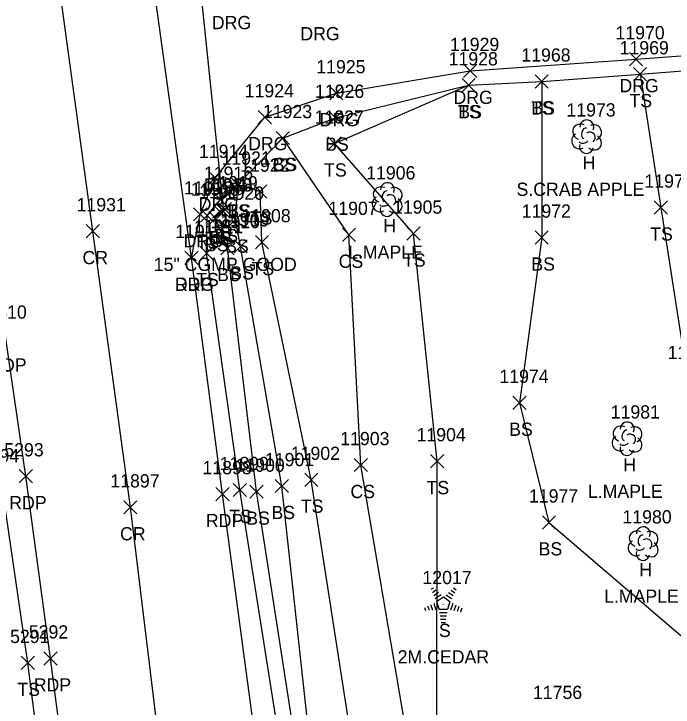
# Model space of a CAD drawing. Extents: x 1439173 to 1457902, y 641926 to 659889.
# Drawn here: x 1447875.7 to 1447975.3, y 648924.6 to 649029.4 of the extents above; entities that cross this region are included whole.
import ezdxf

# ---------------------------------------------------------------- set-up
doc = ezdxf.new("R2010")
doc.units = 0
for name, color, linetype in [('D_A', 7, 'Continuous'), ('D_C', 7, 'Continuous'), ('D_I', 7, 'Continuous'), ('D_TIC', 7, 'Continuous'), ('DCP', 7, 'Continuous'), ('L_A', 7, 'Continuous'), ('L_C', 7, 'Continuous'), ('L_I', 7, 'Continuous'), ('L_TIC', 7, 'Continuous'), ('LELB', 7, 'Continuous'), ('LTC', 7, 'Continuous'), ('LTD', 7, 'Continuous'), ('P_A', 7, 'Continuous'), ('P_I', 7, 'Continuous'), ('P_TIC', 7, 'Continuous'), ('PET', 7, 'Continuous'), ('PRC', 7, 'Continuous'), ('R_A', 7, 'Continuous'), ('R_I', 7, 'Continuous'), ('R_TIC', 7, 'Continuous'), ('RDG', 7, 'Continuous')]:
    doc.layers.add(name, color=color, linetype=linetype)

msp = doc.modelspace()

# ---------------------------------------------------------------- linework, layer by layer
at = {"layer": 'D_TIC'}
for points in [[(1447906.42, 648998.53), (1447908.42, 649000.53)], [(1447908.42, 648998.53), (1447906.42, 649000.53)]]:
    msp.add_lwpolyline(points, dxfattribs=at)
at = {"layer": 'DCP'}
msp.add_lwpolyline([(1447907.42, 648999.53), (1447903.2, 649040.33)], dxfattribs=at)
at = {"layer": 'L_TIC'}
for points in [[(1447969.33, 649019.28), (1447971.33, 649021.28)], [(1447971.33, 649019.28), (1447969.33, 649021.28)], [(1447969.33, 649019.28), (1447971.33, 649021.28)], [(1447971.33, 649019.28), (1447969.33, 649021.28)], [(1447954.47, 649018.18), (1447956.47, 649020.18)], [(1447956.47, 649018.18), (1447954.47, 649020.18)], [(1447954.47, 649018.18), (1447956.47, 649020.18)], [(1447956.47, 649018.18), (1447954.47, 649020.18)], [(1447943.43, 649017.61), (1447945.43, 649019.61)], [(1447945.43, 649017.61), (1447943.43, 649019.61)], [(1447943.43, 649017.61), (1447945.43, 649019.61)], [(1447945.43, 649017.61), (1447943.43, 649019.61)], [(1447923.3, 649012.7), (1447925.3, 649014.7)], [(1447925.3, 649012.7), (1447923.3, 649014.7)], [(1447915.36, 649009.63), (1447917.36, 649011.63)], [(1447917.36, 649009.63), (1447915.36, 649011.63)], [(1447915.36, 649009.63), (1447917.36, 649011.63)], [(1447917.36, 649009.63), (1447915.36, 649011.63)], [(1447923.18, 649008.8), (1447925.18, 649010.8)], [(1447925.18, 649008.8), (1447923.18, 649010.8)], [(1447908.54, 649002.59), (1447910.54, 649004.59)], [(1447910.54, 649002.59), (1447908.54, 649004.59)], [(1447908.54, 649002.59), (1447910.54, 649004.59)], [(1447910.54, 649002.59), (1447908.54, 649004.59)], [(1447911.95, 649001.53), (1447913.95, 649003.53)], [(1447913.95, 649001.53), (1447911.95, 649003.53)], [(1447911.95, 649001.53), (1447913.95, 649003.53)], [(1447913.95, 649001.53), (1447911.95, 649003.53)], [(1447905.94, 649000.32), (1447907.94, 649002.32)], [(1447907.94, 649000.32), (1447905.94, 649002.32)], [(1447905.81, 648998.55), (1447907.81, 649000.55)], [(1447907.81, 648998.55), (1447905.81, 649000.55)], [(1447906.58, 648998.87), (1447908.58, 649000.87)], [(1447908.58, 648998.87), (1447906.58, 649000.87)], [(1447972.46, 648999.12), (1447974.46, 649001.12)], [(1447974.46, 648999.12), (1447972.46, 649001.12)], [(1447903.91, 648997.9), (1447905.91, 648999.9)], [(1447905.91, 648997.9), (1447903.91, 648999.9)], [(1447905.16, 648997.51), (1447907.16, 648999.51)], [(1447907.16, 648997.51), (1447905.16, 648999.51)], [(1447908.19, 648997.29), (1447910.19, 648999.29)], [(1447910.19, 648997.29), (1447908.19, 648999.29)], [(1447908.19, 648997.29), (1447910.19, 648999.29)], [(1447910.19, 648997.29), (1447908.19, 648999.29)], [(1447925.35, 648995), (1447927.35, 648997)], [(1447927.35, 648995), (1447925.35, 648997)], [(1447935.11, 648995.19), (1447937.11, 648997.19)], [(1447937.11, 648995.19), (1447935.11, 648997.19)], [(1447954.47, 648994.58), (1447956.47, 648996.58)], [(1447956.47, 648994.58), (1447954.47, 648996.58)], [(1447906.99, 648992.99), (1447908.99, 648994.99)], [(1447908.99, 648992.99), (1447906.99, 648994.99)], [(1447908.98, 648993.25), (1447910.98, 648995.25)], [(1447910.98, 648993.25), (1447908.98, 648995.25)], [(1447912.2, 648993.89), (1447914.2, 648995.89)], [(1447914.2, 648993.89), (1447912.2, 648995.89)], [(1447903.84, 648992.23), (1447905.84, 648994.23)], [(1447905.84, 648992.23), (1447903.84, 648994.23)], [(1447951.11, 648969.6), (1447953.11, 648971.6)], [(1447953.11, 648969.6), (1447951.11, 648971.6)], [(1447938.66, 648960.78), (1447940.66, 648962.78)], [(1447940.66, 648960.78), (1447938.66, 648962.78)], [(1447927.13, 648960.19), (1447929.13, 648962.19)], [(1447929.13, 648960.19), (1447927.13, 648962.19)], [(1447919.66, 648957.97), (1447921.66, 648959.97)], [(1447921.66, 648957.97), (1447919.66, 648959.97)], [(1447908.85, 648956.42), (1447910.85, 648958.42)], [(1447910.85, 648956.42), (1447908.85, 648958.42)], [(1447915.19, 648957.02), (1447917.19, 648959.02)], [(1447917.19, 648957.02), (1447915.19, 648959.02)], [(1447911.39, 648956.17), (1447913.39, 648958.17)], [(1447913.39, 648956.17), (1447911.39, 648958.17)], [(1447955.57, 648951.52), (1447957.57, 648953.52)], [(1447957.57, 648951.52), (1447955.57, 648953.52)], [(1447876.83, 648930.28), (1447878.83, 648932.28)], [(1447878.83, 648930.28), (1447876.83, 648932.28)]]:
    msp.add_lwpolyline(points, dxfattribs=at)
at = {"layer": 'LELB'}
for points in [[(1447887.67, 648779.22), (1447894.83, 648793.53), (1447889.54, 648830.77), (1447886.45, 648861.56), (1447882.46, 648894.79), (1447877.83, 648931.28), (1447873.82, 648958.59), (1447871.58, 648979.94), (1447867.78, 649009.27), (1447863.09, 649046), (1447856.74, 649083.7)], [(1447970.33, 649020.28), (1448000.68, 649022.67), (1448022.54, 649027.2)], [(1447939.65, 648917.11), (1447939.66, 648961.78), (1447936.11, 648996.19), (1447924.18, 649009.8), (1447944.43, 649018.61), (1447955.47, 649019.18), (1447970.33, 649020.28), (1447973.46, 649000.12), (1447977.53, 648974.21), (1447988.81, 648949.77)], [(1447955.47, 649019.18), (1447955.47, 648995.58), (1447952.11, 648970.6), (1447956.57, 648952.52), (1447981.81, 648930.91)], [(1447974.79, 648514.27), (1447972.12, 648545.7), (1447967.29, 648596.82), (1447958.07, 648647.1), (1447953.07, 648690.28), (1447946.6, 648739.03), (1447940.66, 648780.96), (1447936.37, 648827.1), (1447928.59, 648872.23), (1447920.72, 648916.47), (1447916.19, 648958.02), (1447909.98, 648994.25), (1447909.19, 648998.29), (1447909.54, 649003.59), (1447916.36, 649010.63), (1447924.3, 649013.7), (1447944.43, 649018.61)], [(1447949.69, 648749.17), (1447957, 648759.34), (1447950.28, 648781.04), (1447942.95, 648828.32), (1447936.39, 648874.41), (1447936.04, 648914.65), (1447928.13, 648961.19), (1447926.35, 648996), (1447916.36, 649010.63)], [(1447969.85, 648514.47), (1447964.49, 648544.65), (1447957.95, 648597.38), (1447952.29, 648645.71), (1447946.98, 648689.75), (1447940.5, 648738.3), (1447934.59, 648780.28), (1447929.04, 648824.88), (1447922.4, 648871.3), (1447916.32, 648916.62), (1447909.85, 648957.42), (1447904.84, 648993.23), (1447904.91, 648998.9), (1447906.94, 649001.32), (1447909.54, 649003.59), (1447912.95, 649002.53)], [(1447957.48, 648693.42), (1447950, 648739.49), (1447949.69, 648749.17), (1447943.12, 648781.41), (1447938.92, 648828.83), (1447932.09, 648872.31), (1447927.36, 648915.79), (1447920.66, 648958.97), (1447913.2, 648994.89), (1447912.95, 649002.53)], [(1447971.97, 648514.34), (1447968.59, 648545.51), (1447962.76, 648598.05), (1447955.08, 648646.1), (1447949.31, 648689.51), (1447943.88, 648738.57), (1447940.65, 648781.02), (1447931.82, 648826.68), (1447925.82, 648871.76), (1447918.72, 648916.18), (1447912.39, 648957.17), (1447907.99, 648993.99), (1447906.16, 648998.51), (1447906.81, 648999.55), (1447907.58, 648999.87), (1447909.19, 648998.29)]]:
    msp.add_lwpolyline(points, dxfattribs=at)
at = {"layer": 'LTC'}
for p, q in [((1447938.75, 648942.4), (1447939.1, 648942.65)), ((1447942.15, 648942.64), (1447942.57, 648942.33)), ((1447938.96, 648941.93), (1447939.49, 648942.31)), ((1447939.17, 648941.46), (1447939.87, 648941.98)), ((1447939.38, 648941), (1447940.26, 648941.64)), ((1447941.03, 648941.59), (1447941.84, 648941)), ((1447941.41, 648941.94), (1447942.08, 648941.45)), ((1447941.78, 648942.29), (1447942.33, 648941.89)), ((1447939.6, 648940.54), (1447940.61, 648941.28)), ((1447939.6, 648940.54), (1447939.99, 648939.35)), ((1447940.61, 648941.28), (1447941.61, 648940.55)), ((1447941.61, 648940.55), (1447941.22, 648939.35)), ((1447937.78, 648939.67), (1447937.93, 648939.21)), ((1447938.24, 648939.89), (1447938.45, 648939.24)), ((1447938.69, 648940.11), (1447938.96, 648939.27)), ((1447939.15, 648940.32), (1447939.48, 648939.3)), ((1447941.22, 648939.35), (1447939.99, 648939.35)), ((1447942.05, 648940.28), (1447941.71, 648939.24)), ((1447942.49, 648940.03), (1447942.21, 648939.15)), ((1447942.94, 648939.78), (1447942.7, 648939.05)), ((1447943.38, 648939.53), (1447943.2, 648938.96)), ((1447941.18, 648938.85), (1447940.04, 648938.85)), ((1447941.1, 648938.35), (1447940.11, 648938.35)), ((1447941.01, 648937.85), (1447940.18, 648937.85)), ((1447940.93, 648937.35), (1447940.26, 648937.35))]:
    msp.add_line(p, q, dxfattribs=at)
at = {"layer": 'LTD'}
for p, q in [((1447962.24, 649010.88), (1447962.24, 649010.88)), ((1447962.24, 649010.88), (1447962.24, 649010.88)), ((1447932.1, 649001.37), (1447932.1, 649001.37)), ((1447932.1, 649001.37), (1447932.1, 649001.37)), ((1447968.35, 648965.22), (1447968.35, 648965.22)), ((1447968.35, 648965.22), (1447968.35, 648965.22)), ((1447970.79, 648949.36), (1447970.79, 648949.36)), ((1447970.79, 648949.36), (1447970.79, 648949.36))]:
    msp.add_line(p, q, dxfattribs=at)
for centre in [(1447962.29, 649012.31), (1447932.15, 649002.81), (1447968.4, 648966.65), (1447970.83, 648950.8)]:
    msp.add_arc(centre, 1.05, 335.5272, 180.9563, dxfattribs=at)
for centre, major_axis, ratio, start_param, end_param in [((1447961.45, 649011.54), (1.21, -0.51), 0.895232, 1.570796, 4.712389), ((1447963.28, 649011.46), (-1.14, -0.48), 0.949671, 1.570796, 4.712389), ((1447962.03, 649011.34), (-0.208, -0.792), 0.645439, 3.141593, 6.283185), ((1447962.74, 649010.71), (-0.5, 0.667), 0.989748, 3.141593, 6.283185), ((1447961.16, 649010.17), (0.58, -1.04), 0.959034, 3.141593, 6.283185), ((1447963.24, 649010.04), (-1.09, 0.79), 0.841452, 1.570796, 4.712389), ((1447962.24, 649009.38), (0.26, 1.06), 0.942809, 1.570796, 4.712389), ((1447961.78, 649010.13), (-0.625, -0.083), 0.423636, 0, 3.141593), ((1447931.31, 649002.04), (1.21, -0.51), 0.895232, 1.570796, 4.712389), ((1447933.15, 649001.96), (-1.14, -0.48), 0.949671, 1.570796, 4.712389), ((1447931.9, 649001.83), (-0.208, -0.792), 0.645439, 3.141593, 6.283185), ((1447931.02, 649000.66), (0.58, -1.04), 0.959034, 3.141593, 6.283185), ((1447932.6, 649001.21), (-0.5, 0.667), 0.989748, 3.141593, 6.283185), ((1447933.1, 649000.54), (-1.09, 0.79), 0.841452, 1.570796, 4.712389), ((1447932.11, 648999.87), (0.26, 1.06), 0.942809, 1.570796, 4.712389), ((1447931.65, 649000.62), (-0.625, -0.083), 0.423636, 0, 3.141593), ((1447967.56, 648965.89), (1.21, -0.51), 0.895232, 1.570796, 4.712389), ((1447969.4, 648965.8), (-1.14, -0.48), 0.949671, 1.570796, 4.712389), ((1447967.27, 648964.51), (0.58, -1.04), 0.959034, 3.141593, 6.283185), ((1447968.15, 648965.68), (-0.208, -0.792), 0.645439, 3.141593, 6.283185), ((1447968.85, 648965.05), (-0.5, 0.667), 0.989748, 3.141593, 6.283185), ((1447967.9, 648964.47), (-0.625, -0.083), 0.423636, 0, 3.141593), ((1447969.35, 648964.39), (-1.09, 0.79), 0.841452, 1.570796, 4.712389), ((1447968.35, 648963.72), (0.26, 1.06), 0.942809, 1.570796, 4.712389), ((1447970, 648950.03), (1.21, -0.51), 0.895232, 1.570796, 4.712389), ((1447971.83, 648949.95), (-1.14, -0.48), 0.949671, 1.570796, 4.712389), ((1447970.58, 648949.82), (-0.208, -0.792), 0.645439, 3.141593, 6.283185), ((1447971.29, 648949.2), (-0.5, 0.667), 0.989748, 3.141593, 6.283185), ((1447969.7, 648948.65), (0.58, -1.04), 0.959034, 3.141593, 6.283185), ((1447971.79, 648948.53), (-1.09, 0.79), 0.841452, 1.570796, 4.712389), ((1447970.79, 648947.86), (0.26, 1.06), 0.942809, 1.570796, 4.712389), ((1447970.33, 648948.61), (-0.625, -0.083), 0.423636, 0, 3.141593)]:
    msp.add_ellipse(centre, major_axis=major_axis, ratio=ratio, start_param=start_param, end_param=end_param, dxfattribs=at)
at = {"layer": 'P_TIC'}
for points in [[(1447886.64, 648995.55), (1447888.64, 648997.55)], [(1447888.64, 648995.55), (1447886.64, 648997.55)], [(1447901.54, 648991.52), (1447903.54, 648993.52)], [(1447903.54, 648991.52), (1447901.54, 648993.52)], [(1447876.52, 648958.5), (1447878.52, 648960.5)], [(1447878.52, 648958.5), (1447876.52, 648960.5)], [(1447906.24, 648955.8), (1447908.24, 648957.8)], [(1447908.24, 648955.8), (1447906.24, 648957.8)], [(1447892.31, 648953.8), (1447894.31, 648955.8)], [(1447894.31, 648953.8), (1447892.31, 648955.8)], [(1447880.23, 648930.96), (1447882.23, 648932.96)], [(1447882.23, 648930.96), (1447880.23, 648932.96)]]:
    msp.add_lwpolyline(points, dxfattribs=at)
at = {"layer": 'PET'}
for points in [[(1447899.12, 648797.86), (1447894.84, 648829.94), (1447890.35, 648861.78), (1447886.08, 648894.83), (1447881.23, 648931.96), (1447877.52, 648959.5), (1447874.49, 648980.32), (1447870.94, 649009.61), (1447865.79, 649048.58), (1447861.1, 649084.28)], [(1447985.99, 648352.77), (1447984.12, 648388.61), (1447978.58, 648406.37), (1447976.75, 648417.49), (1447970.56, 648463.48), (1447964.44, 648514.86), (1447960.48, 648544.49), (1447954.4, 648596.97), (1447948.04, 648645.35), (1447942.48, 648689.3), (1447936.15, 648737.63), (1447930.52, 648780.21), (1447924.61, 648825.68), (1447919.43, 648871), (1447912.62, 648916.56), (1447907.24, 648956.8), (1447902.54, 648992.52), (1447895.42, 649044.11)]]:
    msp.add_lwpolyline(points, dxfattribs=at)
at = {"layer": 'PRC'}
msp.add_lwpolyline([(1447922.05, 648736.93), (1447916.64, 648778.15), (1447910.27, 648824.18), (1447904.7, 648868.93), (1447898.12, 648915.43), (1447893.31, 648954.8), (1447887.64, 648996.55), (1447880.91, 649046.05), (1447877.83, 649074.56), (1447871.42, 649121.75), (1447866.3, 649164.93), (1447861.97, 649198.82), (1447856.91, 649237.59), (1447851.83, 649275.88), (1447846.3, 649313.42), (1447840.87, 649352.48), (1447833.11, 649400.15), (1447825.79, 649441.89), (1447815.69, 649490.23), (1447802.04, 649547.27), (1447789.05, 649591.57), (1447772.48, 649642.76), (1447756.88, 649685.17), (1447724.87, 649768.37)], dxfattribs=at)
at = {"layer": 'R_TIC'}
for points in [[(1447968.73, 649021.55), (1447970.73, 649023.55)], [(1447970.73, 649021.55), (1447968.73, 649023.55)], [(1447943.65, 649019.78), (1447945.65, 649021.78)], [(1447945.65, 649019.78), (1447943.65, 649021.78)], [(1447923.44, 649016.41), (1447925.44, 649018.41)], [(1447925.44, 649016.41), (1447923.44, 649018.41)], [(1447912.62, 649012.78), (1447914.62, 649014.78)], [(1447914.62, 649012.78), (1447912.62, 649014.78)], [(1447905.14, 649003.61), (1447907.14, 649005.61)], [(1447907.14, 649003.61), (1447905.14, 649005.61)], [(1447902.86, 648998.09), (1447904.86, 649000.09)], [(1447904.86, 648998.09), (1447902.86, 649000.09)], [(1447901.54, 648991.52), (1447903.54, 648993.52)], [(1447903.54, 648991.52), (1447901.54, 648993.52)]]:
    msp.add_lwpolyline(points, dxfattribs=at)
at = {"layer": 'RDG'}
msp.add_lwpolyline([(1447902.54, 648992.52), (1447903.86, 648999.09), (1447906.14, 649004.61), (1447913.62, 649013.78), (1447924.44, 649017.41), (1447944.65, 649020.78), (1447969.73, 649022.55), (1448000.78, 649024.89), (1448022.47, 649028.53), (1448027.87, 649029.39), (1448036.37, 649028.16)], dxfattribs=at)

# ---------------------------------------------------------------- texts
at = {"layer": 'D_A'}
msp.add_text('P', height=2, dxfattribs=at).set_placement((1447906.8, 648994.53))
at = {"layer": 'D_C'}
msp.add_text('15" CGMP GOOD', height=2, dxfattribs=at).set_placement((1447896.85, 648990.53))
at = {"layer": 'D_I'}
msp.add_text('11930', height=2, dxfattribs=at).set_placement((1447904.31, 649002.53))
at = {"layer": 'L_A'}
for s, p in [('TS', (1447968.74, 649015.28)), ('TS', (1447968.74, 649015.28)), ('TS', (1447953.88, 649014.18)), ('BS', (1447953.91, 649014.18)), ('TS', (1447942.84, 649013.61)), ('BS', (1447942.87, 649013.61)), ('BS', (1447922.74, 649008.7)), ('CS', (1447914.8, 649005.63)), ('BS', (1447914.8, 649005.63)), ('H', (1447961.67, 649005.88)), ('TS', (1447922.59, 649004.8)), ('TS', (1447907.95, 648998.59)), ('BS', (1447907.98, 648998.59)), ('TS', (1447911.36, 648997.53)), ('TS', (1447911.36, 648997.53)), ('TS', (1447905.35, 648996.32)), ('H', (1447931.54, 648996.37)), ('TS', (1447971.87, 648995.12)), ('TS', (1447903.32, 648993.9)), ('BS', (1447905.25, 648994.55)), ('BS', (1447906.02, 648994.87)), ('BS', (1447904.6, 648993.51)), ('BS', (1447907.63, 648993.29)), ('BS', (1447907.63, 648993.29)), ('CS', (1447924.79, 648991)), ('TS', (1447934.52, 648991.19)), ('TS', (1447911.61, 648989.89)), ('BS', (1447953.91, 648990.58)), ('BS', (1447906.43, 648988.99)), ('BS', (1447908.42, 648989.25)), ('TS', (1447903.25, 648988.23)), ('BS', (1447950.55, 648965.6)), ('H', (1447967.79, 648960.22)), ('CS', (1447926.57, 648956.19)), ('TS', (1447938.07, 648956.78)), ('TS', (1447919.07, 648953.97)), ('TS', (1447908.26, 648952.42)), ('BS', (1447910.83, 648952.17)), ('BS', (1447914.63, 648953.02)), ('BS', (1447955.01, 648947.52)), ('H', (1447970.22, 648944.36)), ('S', (1447939.94, 648935.19)), ('TS', (1447876.24, 648926.28))]:
    msp.add_text(s, height=2, dxfattribs=at).set_placement(p)
at = {"layer": 'L_C'}
for s, p in [('S.CRAB APPLE', (1447951.67, 649001.88)), ('L.MAPLE', (1447926.22, 648992.37)), ('L.MAPLE', (1447962.46, 648956.22)), ('L.MAPLE', (1447964.9, 648940.36)), ('2M.CEDAR', (1447933.71, 648931.19))]:
    msp.add_text(s, height=2, dxfattribs=at).set_placement(p)
at = {"layer": 'L_I'}
for s, p in [('11969', (1447967.25, 649023.28)), ('11969', (1447967.25, 649023.28)), ('11928', (1447941.41, 649021.61)), ('11928', (1447941.41, 649021.61)), ('11968', (1447952.4, 649022.18)), ('11968', (1447952.4, 649022.18)), ('11926', (1447921.22, 649016.7)), ('11973', (1447959.21, 649013.88)), ('11923', (1447913.34, 649013.63)), ('11923', (1447913.34, 649013.63)), ('11927', (1447921.16, 649012.8)), ('11921', (1447907.09, 649006.59)), ('11921', (1447907.09, 649006.59)), ('11922', (1447909.92, 649005.53)), ('11922', (1447909.92, 649005.53)), ('11916', (1447904.43, 649004.32)), ('11906', (1447928.95, 649004.37)), ('11918', (1447904.35, 649002.55)), ('11919', (1447905.12, 649002.87)), ('11971', (1447971, 649003.12)), ('11915', (1447902.45, 649001.9)), ('11917', (1447903.7, 649001.51)), ('11920', (1447906.08, 649001.29)), ('11920', (1447906.08, 649001.29)), ('11905', (1447933.01, 648999.19)), ('11907', (1447923.25, 648999)), ('11972', (1447952.45, 648998.58)), ('11909', (1447906.87, 648997.25)), ('11908', (1447910.1, 648997.89)), ('11911', (1447902.95, 648996.23)), ('11910', (1447905.45, 648996.99)), ('11975', (1447974.5, 648977.21)), ('11974', (1447949.08, 648973.6)), ('11981', (1447965.9, 648968.22)), ('11904', (1447936.56, 648964.78)), ('11903', (1447925.03, 648964.19)), ('5294', (1447870.56, 648961.59)), ('11902', (1447917.56, 648961.97)), ('11899', (1447906.82, 648960.42)), ('11901', (1447913.65, 648961.02)), ('11900', (1447909.2, 648960.17)), ('11977', (1447953.55, 648955.52)), ('11980', (1447967.68, 648952.36)), ('12017', (1447937.45, 648943.19)), ('5291', (1447875.14, 648934.28)), ('11756', (1447954.15, 648925.82)), ('11756', (1447954.15, 648925.82)), ('11756', (1447954.15, 648925.82))]:
    msp.add_text(s, height=2, dxfattribs=at).set_placement(p)
at = {"layer": 'LTC'}
msp.add_text('.', height=1.04, rotation=270, dxfattribs=at).set_placement((1447940.5, 648940.29))
at = {"layer": 'P_A'}
for s, p in [('CR', (1447886.08, 648991.55)), ('RDP', (1447900.03, 648987.52)), ('RDP', (1447871.98, 648975.32)), ('RDP', (1447875.01, 648954.5)), ('RDP', (1447904.72, 648951.8)), ('CR', (1447891.75, 648949.8)), ('RDP', (1447878.72, 648926.96))]:
    msp.add_text(s, height=2, dxfattribs=at).set_placement(p)
at = {"layer": 'P_I'}
for s, p in [('11931', (1447885.19, 648999.55)), ('11912', (1447900.09, 648995.52)), ('5310', (1447871.71, 648983.32)), ('5293', (1447874.26, 648962.5)), ('11898', (1447904.21, 648959.8)), ('11897', (1447890.29, 648957.8)), ('5292', (1447877.97, 648934.96))]:
    msp.add_text(s, height=2, dxfattribs=at).set_placement(p)
at = {"layer": 'R_A'}
for p in [(1447905.63, 649027.08), (1447919, 649025.4), (1447967.22, 649017.55), (1447942.14, 649015.78), (1447921.92, 649012.41), (1447911.11, 649008.78), (1447903.63, 648999.61), (1447901.35, 648994.09), (1447900.03, 648987.52)]:
    msp.add_text('DRG', height=2, dxfattribs=at).set_placement(p)
at = {"layer": 'R_I'}
for s, p in [('11970', (1447966.62, 649025.55)), ('11929', (1447941.62, 649023.78)), ('11925', (1447921.41, 649020.41)), ('11924', (1447910.59, 649016.78)), ('11914', (1447903.68, 649007.61)), ('11913', (1447901.41, 649002.09)), ('11912', (1447900.09, 648995.52))]:
    msp.add_text(s, height=2, dxfattribs=at).set_placement(p)

doc.saveas('drawing.dxf')
